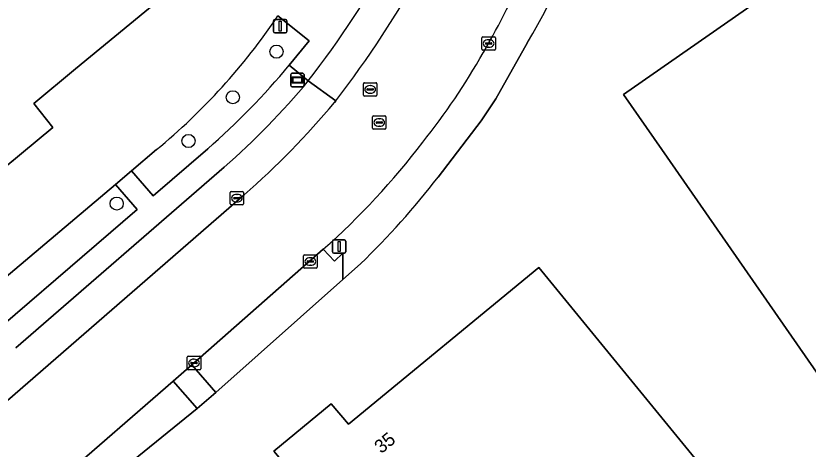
# Model space of a CAD drawing. Extents: x 156702 to 158052, y 387630 to 388992.
# Drawn here: x 157269.3 to 157328.3, y 387774.5 to 387806.8 of the extents above; entities that cross this region are included whole.
import ezdxf

# ---------------------------------------------------------------- set-up
doc = ezdxf.new("R2010")
doc.units = 0
for name, color, linetype in [('IMGEO_Boom', 7, 'Continuous'), ('IMGEO_Erf', 7, 'Continuous'), ('IMGEO_Groenvoorziening', 7, 'Continuous'), ('IMGEO_Informatiebord', 7, 'Continuous'), ('IMGEO_Kolk', 7, 'Continuous'), ('IMGEO_Lichtmast', 7, 'Continuous'), ('IMGEO_Pand', 7, 'Continuous'), ('IMGEO_Pand_nummerreeks', 7, 'Continuous'), ('IMGEO_Parkeervlak_open', 7, 'Continuous'), ('IMGEO_Rijbaan_lokaal_gesloten', 7, 'Continuous'), ('IMGEO_Rioolput', 7, 'Continuous'), ('IMGEO_Verkeersbordpaal', 7, 'Continuous'), ('IMGEO_Voetpad_open', 7, 'Continuous')]:
    doc.layers.add(name, color=color, linetype=linetype)

msp = doc.modelspace()

# ---------------------------------------------------------------- linework, layer by layer
at = {"layer": 'IMGEO_Boom'}
for centre in [(157288.701, 387804.11), (157285.448, 387800.716), (157282.148, 387797.464), (157276.803, 387792.806)]:
    msp.add_circle(centre, 0.489, dxfattribs=at)
at = {"layer": 'IMGEO_Erf'}
for points in [[(157278.484, 387870.163), (157299.316, 387844.802), (157291.542, 387838.402), (157280.697, 387829.474), (157285.889, 387823.145), (157279.697, 387818.085), (157284.76, 387811.91), (157273.737, 387802.823), (157270.622, 387800.255), (157272.057, 387798.475), (157266.039, 387793.519), (157255.901, 387805.842), (157261.926, 387810.809), (157262.25, 387810.377), (157263.979, 387811.778), (157249.792, 387829.047), (157249.636, 387829.236), (157246.596, 387832.937), (157246.438, 387833.129), (157243.382, 387836.849), (157243.219, 387837.048), (157241.16, 387839.554), (157259.836, 387854.902)], [(157363.539, 387777.795), (157348.61, 387751.927), (157317.395, 387796.828), (157314.541, 387800.934), (157324.263, 387807.695), (157318.792, 387815.594), (157321.059, 387817.16), (157323.754, 387824.051), (157322.937, 387825.336), (157325.523, 387832.18), (157329.304, 387826.757), (157336.59, 387816.266), (157336.718, 387816.356), (157339.573, 387812.251)], [(157378.748, 387694.956), (157361.772, 387681), (157364.016, 387678.262), (157358.146, 387673.452), (157342.053, 387693.048), (157343.568, 387694.292), (157319.361, 387723.831), (157319.262, 387723.952), (157297.863, 387750), (157292.107, 387757.007), (157290.591, 387755.753), (157280.605, 387767.928), (157286.246, 387772.551), (157287.377, 387771.317), (157289.551, 387773.149), (157288.491, 387774.397), (157292.77, 387777.908), (157294.05, 387776.396), (157308.228, 387788.046), (157339.41, 387750), (157344.144, 387744.224), (157340.665, 387741.338)]]:
    msp.add_lwpolyline(points, close=True, dxfattribs=at)
for points in [[(157307.397, 387804.794), (157305.043, 387800.595), (157303.942, 387798.962), (157300.737, 387794.775)], [(157265.834, 387785.07), (157276.702, 387794.234), (157277.903, 387795.246), (157279.77, 387796.82)], [(157294.955, 387788.331), (157293.629, 387787.152), (157284.18, 387778.754), (157282.784, 387777.576), (157273.993, 387770.42)]]:
    msp.add_lwpolyline(points, dxfattribs=at)
for centre, radius, start, end in [((157232.637, 387848.1), 86.397, 329.91795, 338.04808), ((157249.773, 387833.157), 47.119, 309.53976, 325.94611), ((157253.544, 387831.304), 59.679, 313.9397, 322.25903)]:
    msp.add_arc(centre, radius, start, end, dxfattribs=at)
at = {"layer": 'IMGEO_Groenvoorziening'}
for points in [[(157289.642, 387803.1), (157291.142, 387804.921), (157288.812, 387806.772)], [(157279.77, 387796.82), (157277.903, 387795.246), (157279.511, 387793.395), (157283.578, 387796.887)], [(157262.209, 387782.917), (157264.231, 387780.276), (157278.319, 387792.372), (157276.702, 387794.234), (157265.834, 387785.07)]]:
    msp.add_lwpolyline(points, dxfattribs=at)
for points in [[(157293.629, 387787.152), (157293.651, 387789.12), (157293.018, 387788.525), (157292.183, 387789.406), (157282.385, 387780.806), (157284.18, 387778.754)], [(157273.993, 387770.42), (157282.784, 387777.576), (157281.01, 387779.609), (157272.493, 387772.206)]]:
    msp.add_lwpolyline(points, close=True, dxfattribs=at)
for centre, radius, start, end in [((157249.773, 387833.157), 47.119, 309.53976, 325.94611), ((157247.514, 387838.152), 54.803, 311.15224, 320.23843)]:
    msp.add_arc(centre, radius, start, end, dxfattribs=at)
at = {"layer": 'IMGEO_Informatiebord'}
for p, q in [((157289.862, 387802.498), (157290.652, 387802.498)), ((157290.652, 387802.498), (157289.862, 387802.498)), ((157289.762, 387801.598), (157289.762, 387802.398)), ((157289.762, 387802.398), (157289.762, 387801.598)), ((157290.752, 387802.398), (157290.752, 387801.598)), ((157290.752, 387801.598), (157290.752, 387802.398)), ((157290.652, 387801.498), (157289.862, 387801.498)), ((157289.862, 387801.498), (157290.652, 387801.498))]:
    msp.add_line(p, q, dxfattribs=at)
for points in [[(157289.863, 387802.23), (157290.651, 387802.23), (157290.651, 387801.766), (157289.863, 387801.766), (157289.863, 387802.23)], [(157289.928, 387802.165), (157289.928, 387801.831), (157290.586, 387801.831), (157290.586, 387802.165), (157289.928, 387802.165)]]:
    msp.add_lwpolyline(points, dxfattribs=at)
for centre, start, end in [((157289.862, 387802.398), 90, 180), ((157289.862, 387802.398), 90, 180), ((157290.652, 387802.398), 0, 90), ((157290.652, 387802.398), 360, 90), ((157289.862, 387801.598), 180, 270), ((157289.862, 387801.598), 180, 270), ((157290.652, 387801.598), 270, 0), ((157290.652, 387801.598), 270, 0)]:
    msp.add_arc(centre, 0.1, start, end, dxfattribs=at)
at = {"layer": 'IMGEO_Kolk'}
for p, q in [((157303.997, 387804.287), (157303.997, 387805.139)), ((157304.072, 387805.213), (157304.924, 387805.213)), ((157304.485, 387804.993), (157304.51, 387804.993)), ((157304.998, 387805.139), (157304.998, 387804.287)), ((157304.924, 387804.213), (157304.072, 387804.213)), ((157304.256, 387804.707), (157304.256, 387804.719)), ((157304.694, 387804.67), (157304.296, 387804.67)), ((157304.299, 387804.756), (157304.697, 387804.756)), ((157304.508, 387804.433), (157304.483, 387804.433)), ((157304.74, 387804.719), (157304.74, 387804.707)), ((157285.251, 387792.783), (157285.251, 387793.635)), ((157285.326, 387793.709), (157286.178, 387793.709)), ((157286.252, 387793.635), (157286.252, 387792.783)), ((157285.51, 387793.203), (157285.51, 387793.215)), ((157285.948, 387793.166), (157285.55, 387793.166)), ((157285.553, 387793.252), (157285.951, 387793.252)), ((157285.739, 387793.489), (157285.764, 387793.489)), ((157285.994, 387793.215), (157285.994, 387793.203)), ((157286.178, 387792.709), (157285.326, 387792.709)), ((157285.762, 387792.929), (157285.737, 387792.929)), ((157290.723, 387788.073), (157290.723, 387788.925)), ((157290.798, 387788.999), (157291.65, 387788.999)), ((157291.724, 387788.925), (157291.724, 387788.073)), ((157290.982, 387788.493), (157290.982, 387788.505)), ((157291.42, 387788.456), (157291.022, 387788.456)), ((157291.025, 387788.542), (157291.423, 387788.542)), ((157291.211, 387788.779), (157291.236, 387788.779)), ((157291.466, 387788.505), (157291.466, 387788.493)), ((157291.65, 387787.999), (157290.798, 387787.999)), ((157291.234, 387788.219), (157291.209, 387788.219)), ((157282.058, 387780.526), (157282.058, 387781.378)), ((157282.133, 387781.452), (157282.985, 387781.452)), ((157282.546, 387781.232), (157282.571, 387781.232)), ((157283.059, 387781.378), (157283.059, 387780.526)), ((157282.317, 387780.946), (157282.317, 387780.958)), ((157282.755, 387780.909), (157282.357, 387780.909)), ((157282.36, 387780.995), (157282.758, 387780.995)), ((157282.569, 387780.672), (157282.544, 387780.672)), ((157282.801, 387780.958), (157282.801, 387780.946)), ((157282.985, 387780.452), (157282.133, 387780.452))]:
    msp.add_line(p, q, dxfattribs=at)
for points in [[(157303.997, 387804.287), (157303.997, 387805.139)], [(157304.072, 387805.213), (157304.924, 387805.213)], [(157304.998, 387805.139), (157304.998, 387804.287)], [(157304.924, 387804.213), (157304.072, 387804.213)], [(157285.251, 387792.783), (157285.251, 387793.635)], [(157285.326, 387793.709), (157286.178, 387793.709)], [(157286.252, 387793.635), (157286.252, 387792.783)], [(157286.178, 387792.709), (157285.326, 387792.709)], [(157290.723, 387788.073), (157290.723, 387788.925)], [(157290.798, 387788.999), (157291.65, 387788.999)], [(157291.724, 387788.925), (157291.724, 387788.073)], [(157291.65, 387787.999), (157290.798, 387787.999)], [(157282.058, 387780.526), (157282.058, 387781.378)], [(157282.133, 387781.452), (157282.985, 387781.452)], [(157283.059, 387781.378), (157283.059, 387780.526)], [(157282.985, 387780.452), (157282.133, 387780.452)]]:
    msp.add_lwpolyline(points, dxfattribs=at)
for centre, radius, start, end in [((157304.074, 387805.137), 0.0765, 91.55205, 178.44795), ((157304.074, 387805.137), 0.0765, 91.55205, 178.44795), ((157304.922, 387805.137), 0.0765, 1.55205, 88.44795), ((157304.922, 387805.137), 0.0765, 1.55205, 88.44795), ((157304.074, 387804.289), 0.0765, 181.55205, 268.44795), ((157304.074, 387804.289), 0.0765, 181.55205, 268.44795), ((157304.296, 387804.716), 0.0403, 85.87752, 175.75265), ((157304.293, 387804.706), 0.0366, 178.93798, 274.71019), ((157304.697, 387804.713), 0.043, 264.86636, 352.45326), ((157304.701, 387804.718), 0.0386, 1.73085, 96.63898), ((157304.922, 387804.289), 0.0765, 271.55205, 358.44795), ((157304.922, 387804.289), 0.0765, 271.55205, 358.44795), ((157285.328, 387793.633), 0.0765, 91.55205, 178.44795), ((157285.328, 387793.633), 0.0765, 91.55205, 178.44795), ((157286.176, 387793.633), 0.0765, 1.55205, 88.44795), ((157286.176, 387793.633), 0.0765, 1.55205, 88.44795), ((157285.55, 387793.212), 0.0403, 85.87752, 175.75265), ((157285.547, 387793.202), 0.0366, 178.93798, 274.71019), ((157285.951, 387793.209), 0.043, 264.86636, 352.45326), ((157285.955, 387793.214), 0.0386, 1.73085, 96.63898), ((157285.328, 387792.785), 0.0765, 181.55205, 268.44795), ((157285.328, 387792.785), 0.0765, 181.55205, 268.44795), ((157286.176, 387792.785), 0.0765, 271.55205, 358.44795), ((157286.176, 387792.785), 0.0765, 271.55205, 358.44795), ((157290.8, 387788.923), 0.0765, 91.55205, 178.44795), ((157290.8, 387788.923), 0.0765, 91.55205, 178.44795), ((157291.648, 387788.923), 0.0765, 1.55205, 88.44795), ((157291.648, 387788.923), 0.0765, 1.55205, 88.44795), ((157291.022, 387788.502), 0.0403, 85.87752, 175.75265), ((157291.019, 387788.492), 0.0366, 178.93798, 274.71019), ((157291.423, 387788.499), 0.043, 264.86636, 352.45326), ((157291.427, 387788.504), 0.0386, 1.73085, 96.63898), ((157290.8, 387788.075), 0.0765, 181.55205, 268.44795), ((157290.8, 387788.075), 0.0765, 181.55205, 268.44795), ((157291.648, 387788.075), 0.0765, 271.55205, 358.44795), ((157291.648, 387788.075), 0.0765, 271.55205, 358.44795), ((157282.135, 387781.376), 0.0765, 91.55205, 178.44795), ((157282.135, 387781.376), 0.0765, 91.55205, 178.44795), ((157282.983, 387781.376), 0.0765, 1.55205, 88.44795), ((157282.983, 387781.376), 0.0765, 1.55205, 88.44795), ((157282.357, 387780.955), 0.0403, 85.87752, 175.75265), ((157282.354, 387780.945), 0.0366, 178.93798, 274.71019), ((157282.758, 387780.952), 0.043, 264.86636, 352.45326), ((157282.762, 387780.957), 0.0386, 1.73085, 96.63898), ((157282.135, 387780.528), 0.0765, 181.55205, 268.44795), ((157282.135, 387780.528), 0.0765, 181.55205, 268.44795), ((157282.983, 387780.528), 0.0765, 271.55205, 358.44795), ((157282.983, 387780.528), 0.0765, 271.55205, 358.44795)]:
    msp.add_arc(centre, radius, start, end, dxfattribs=at)
for centre, major_axis, ratio, start_param, end_param in [((157304.484, 387804.713), (-0.387, 0.002), 0.722429, 4.712389, 7.853982), ((157304.509, 387804.713), (-0.39, 0.002), 0.717154, 1.570796, 4.712389), ((157285.738, 387793.209), (-0.387, 0.002), 0.722429, 4.712389, 7.853982), ((157285.763, 387793.209), (-0.39, 0.002), 0.717154, 1.570796, 4.712389), ((157291.21, 387788.499), (-0.387, 0.002), 0.722429, 4.712389, 7.853982), ((157291.235, 387788.499), (-0.39, 0.002), 0.717154, 1.570796, 4.712389), ((157282.545, 387780.952), (-0.387, 0.002), 0.722429, 4.712389, 7.853982), ((157282.57, 387780.952), (-0.39, 0.002), 0.717154, 1.570796, 4.712389)]:
    msp.add_ellipse(centre, major_axis=major_axis, ratio=ratio, start_param=start_param, end_param=end_param, dxfattribs=at)
at = {"layer": 'IMGEO_Lichtmast'}
for p, q in [((157292.865, 387789.215), (157292.865, 387790.015)), ((157292.865, 387790.015), (157292.865, 387789.215)), ((157292.965, 387790.115), (157293.755, 387790.115)), ((157293.755, 387790.115), (157292.965, 387790.115)), ((157293.855, 387790.015), (157293.855, 387789.215)), ((157293.855, 387789.215), (157293.855, 387790.015)), ((157293.755, 387789.115), (157292.965, 387789.115)), ((157292.965, 387789.115), (157293.755, 387789.115))]:
    msp.add_line(p, q, dxfattribs=at)
msp.add_lwpolyline([(157293.285, 387789.99), (157293.435, 387789.99), (157293.435, 387789.24), (157293.285, 387789.24), (157293.285, 387789.99)], dxfattribs=at)
for centre, start, end in [((157292.965, 387790.015), 90, 180), ((157292.965, 387790.015), 90, 180), ((157293.755, 387790.015), 0, 90), ((157293.755, 387790.015), 360, 90), ((157292.965, 387789.215), 180, 270), ((157292.965, 387789.215), 180, 270), ((157293.755, 387789.215), 270, 0), ((157293.755, 387789.215), 270, 0)]:
    msp.add_arc(centre, 0.1, start, end, dxfattribs=at)
at = {"layer": 'IMGEO_Pand'}
for points in [[(157249.792, 387829.047), (157263.979, 387811.778), (157262.25, 387810.377), (157261.926, 387810.809), (157255.901, 387805.842), (157266.039, 387793.519), (157272.057, 387798.475), (157270.622, 387800.255), (157273.737, 387802.823), (157284.76, 387811.91), (157279.697, 387818.085), (157285.889, 387823.145), (157280.697, 387829.474), (157291.542, 387838.402), (157299.316, 387844.802), (157278.484, 387870.163), (157259.836, 387854.902), (157241.16, 387839.554), (157243.219, 387837.048), (157243.382, 387836.849), (157246.438, 387833.129), (157246.596, 387832.937), (157249.636, 387829.236)], [(157336.718, 387816.356), (157336.59, 387816.266), (157329.304, 387826.757), (157325.523, 387832.18), (157322.937, 387825.336), (157323.754, 387824.051), (157321.059, 387817.16), (157318.792, 387815.594), (157324.263, 387807.695), (157314.541, 387800.934), (157317.395, 387796.828), (157348.61, 387751.927), (157363.539, 387777.795), (157339.573, 387812.251)], [(157319.361, 387723.831), (157340.665, 387741.338), (157344.144, 387744.224), (157339.41, 387750), (157308.228, 387788.046), (157294.05, 387776.396), (157292.77, 387777.908), (157288.491, 387774.397), (157289.551, 387773.149), (157287.377, 387771.317), (157286.246, 387772.551), (157280.605, 387767.928), (157290.591, 387755.753), (157292.107, 387757.007), (157297.863, 387750), (157319.262, 387723.952)]]:
    msp.add_lwpolyline(points, close=True, dxfattribs=at)
at = {"layer": 'IMGEO_Parkeervlak_open'}
for points in [[(157293.014, 387800.321), (157293.119, 387800.457), (157291.063, 387801.929)], [(157284.808, 387795.507), (157269.292, 387782.069)], [(157268.085, 387777.663), (157286.301, 387793.452)]]:
    msp.add_lwpolyline(points, dxfattribs=at)
for centre, radius, start, end in [((157245.148, 387840.393), 59.897, 311.46298, 320.0465), ((157244.168, 387841.343), 63.786, 311.34034, 319.97578)]:
    msp.add_arc(centre, radius, start, end, dxfattribs=at)
at = {"layer": 'IMGEO_Rijbaan_lokaal_gesloten'}
for points in [[(157304.091, 387804.034), (157304.594, 387804.903)], [(157293.119, 387800.457), (157293.014, 387800.321)], [(157286.301, 387793.452), (157268.085, 387777.663), (157267.868, 387777.475), (157266.365, 387776.435), (157265.591, 387776.039), (157265.488, 387775.964)], [(157281.01, 387779.609), (157282.385, 387780.806), (157292.183, 387789.406)], [(157270.059, 387770.045), (157270.681, 387770.652), (157272.381, 387772.11), (157272.493, 387772.206), (157281.01, 387779.609)]]:
    msp.add_lwpolyline(points, dxfattribs=at)
for centre, radius, start, end in [((157231.904, 387847.749), 77.355, 322.31186, 339.92433), ((157200.407, 387861.75), 118.687, 331.382, 338.18195), ((157260.794, 387828.461), 49.712, 321.29212, 330.56876), ((157244.168, 387841.343), 63.786, 311.34034, 319.97578), ((157255.479, 387830.935), 55.424, 311.47006, 322.73243)]:
    msp.add_arc(centre, radius, start, end, dxfattribs=at)
at = {"layer": 'IMGEO_Rioolput'}
for p, q in [((157295.176, 387800.874), (157295.176, 387801.726)), ((157295.251, 387801.8), (157296.103, 387801.8)), ((157295.435, 387801.294), (157295.435, 387801.306)), ((157295.873, 387801.257), (157295.475, 387801.257)), ((157295.478, 387801.343), (157295.876, 387801.343)), ((157295.664, 387801.58), (157295.689, 387801.58)), ((157295.919, 387801.306), (157295.919, 387801.294)), ((157296.177, 387801.726), (157296.177, 387800.874)), ((157296.103, 387800.8), (157295.251, 387800.8)), ((157295.687, 387801.02), (157295.662, 387801.02)), ((157295.852, 387798.409), (157295.852, 387799.261)), ((157295.927, 387799.335), (157296.779, 387799.335)), ((157296.154, 387798.878), (157296.552, 387798.878)), ((157296.34, 387799.115), (157296.365, 387799.115)), ((157296.853, 387799.261), (157296.853, 387798.409)), ((157296.779, 387798.335), (157295.927, 387798.335)), ((157296.111, 387798.829), (157296.111, 387798.841)), ((157296.549, 387798.792), (157296.151, 387798.792)), ((157296.363, 387798.555), (157296.338, 387798.555)), ((157296.595, 387798.841), (157296.595, 387798.829))]:
    msp.add_line(p, q, dxfattribs=at)
for points in [[(157295.176, 387800.874), (157295.176, 387801.726)], [(157295.251, 387801.8), (157296.103, 387801.8)], [(157296.177, 387801.726), (157296.177, 387800.874)], [(157296.103, 387800.8), (157295.251, 387800.8)], [(157295.852, 387798.409), (157295.852, 387799.261)], [(157295.927, 387799.335), (157296.779, 387799.335)], [(157296.853, 387799.261), (157296.853, 387798.409)], [(157296.779, 387798.335), (157295.927, 387798.335)]]:
    msp.add_lwpolyline(points, dxfattribs=at)
for centre, radius, start, end in [((157295.253, 387801.724), 0.0765, 91.55205, 178.44795), ((157295.253, 387801.724), 0.0765, 91.55205, 178.44795), ((157295.475, 387801.303), 0.0403, 85.87752, 175.75265), ((157295.472, 387801.293), 0.0366, 178.93798, 274.71019), ((157295.876, 387801.3), 0.043, 264.86636, 352.45326), ((157295.88, 387801.305), 0.0386, 1.73085, 96.63898), ((157296.101, 387801.724), 0.0765, 1.55205, 88.44795), ((157296.101, 387801.724), 0.0765, 1.55205, 88.44795), ((157295.253, 387800.876), 0.0765, 181.55205, 268.44795), ((157295.253, 387800.876), 0.0765, 181.55205, 268.44795), ((157296.101, 387800.876), 0.0765, 271.55205, 358.44795), ((157296.101, 387800.876), 0.0765, 271.55205, 358.44795), ((157295.929, 387799.259), 0.0765, 91.55205, 178.44795), ((157295.929, 387799.259), 0.0765, 91.55205, 178.44795), ((157296.151, 387798.838), 0.0403, 85.87752, 175.75265), ((157296.556, 387798.84), 0.0386, 1.73085, 96.63898), ((157296.777, 387799.259), 0.0765, 1.55205, 88.44795), ((157296.777, 387799.259), 0.0765, 1.55205, 88.44795), ((157295.929, 387798.411), 0.0765, 181.55205, 268.44795), ((157295.929, 387798.411), 0.0765, 181.55205, 268.44795), ((157296.148, 387798.828), 0.0366, 178.93798, 274.71019), ((157296.552, 387798.835), 0.043, 264.86636, 352.45326), ((157296.777, 387798.411), 0.0765, 271.55205, 358.44795), ((157296.777, 387798.411), 0.0765, 271.55205, 358.44795)]:
    msp.add_arc(centre, radius, start, end, dxfattribs=at)
for centre, major_axis, ratio, start_param, end_param in [((157295.663, 387801.3), (-0.387, 0.002), 0.722429, 4.712389, 7.853982), ((157295.688, 387801.3), (-0.39, 0.002), 0.717154, 1.570796, 4.712389), ((157296.339, 387798.835), (-0.387, 0.002), 0.722429, 4.712389, 7.853982), ((157296.364, 387798.835), (-0.39, 0.002), 0.717154, 1.570796, 4.712389)]:
    msp.add_ellipse(centre, major_axis=major_axis, ratio=ratio, start_param=start_param, end_param=end_param, dxfattribs=at)
at = {"layer": 'IMGEO_Verkeersbordpaal'}
for p, q in [((157288.475, 387805.607), (157288.475, 387806.407)), ((157288.475, 387806.407), (157288.475, 387805.607)), ((157288.575, 387806.507), (157289.365, 387806.507)), ((157289.365, 387806.507), (157288.575, 387806.507)), ((157289.465, 387806.407), (157289.465, 387805.607)), ((157289.465, 387805.607), (157289.465, 387806.407)), ((157289.365, 387805.507), (157288.575, 387805.507)), ((157288.575, 387805.507), (157289.365, 387805.507))]:
    msp.add_line(p, q, dxfattribs=at)
msp.add_lwpolyline([(157288.895, 387806.382), (157289.045, 387806.382), (157289.045, 387805.632), (157288.895, 387805.632), (157288.895, 387806.382)], dxfattribs=at)
for centre, start, end in [((157288.575, 387806.407), 90, 180), ((157288.575, 387806.407), 90, 180), ((157289.365, 387806.407), 0, 90), ((157289.365, 387806.407), 360, 90), ((157288.575, 387805.607), 180, 270), ((157288.575, 387805.607), 180, 270), ((157289.365, 387805.607), 270, 0), ((157289.365, 387805.607), 270, 0)]:
    msp.add_arc(centre, 0.1, start, end, dxfattribs=at)
at = {"layer": 'IMGEO_Voetpad_open'}
for points in [[(157288.812, 387806.772), (157291.142, 387804.921), (157289.642, 387803.1), (157291.063, 387801.929)], [(157300.737, 387794.775), (157303.942, 387798.962), (157305.043, 387800.595), (157307.397, 387804.794)], [(157304.594, 387804.903), (157304.091, 387804.034)], [(157291.063, 387801.929), (157289.642, 387803.1)], [(157291.063, 387801.929), (157293.119, 387800.457)], [(157283.578, 387796.887), (157279.511, 387793.395), (157277.903, 387795.246), (157276.702, 387794.234), (157278.319, 387792.372), (157264.231, 387780.276)], [(157269.292, 387782.069), (157284.808, 387795.507)], [(157292.183, 387789.406), (157293.018, 387788.525), (157293.651, 387789.12), (157293.629, 387787.152), (157294.955, 387788.331)]]:
    msp.add_lwpolyline(points, dxfattribs=at)
msp.add_lwpolyline([(157281.01, 387779.609), (157282.784, 387777.576), (157284.18, 387778.754), (157282.385, 387780.806)], close=True, dxfattribs=at)
for centre, radius, start, end in [((157231.182, 387848.181), 75.663, 322.31758, 339.85782), ((157231.182, 387848.181), 75.663, 322.31758, 339.85782), ((157231.904, 387847.749), 77.355, 322.31186, 339.92433), ((157200.407, 387861.75), 118.687, 331.382, 338.18195), ((157232.637, 387848.1), 86.397, 329.91795, 338.04808), ((157260.794, 387828.461), 49.712, 321.29212, 330.56876), ((157247.514, 387838.152), 54.803, 311.15224, 320.23843), ((157245.148, 387840.393), 59.897, 311.46298, 320.0465), ((157255.479, 387830.935), 55.424, 311.47006, 322.73243), ((157253.544, 387831.304), 59.679, 313.9397, 322.25903)]:
    msp.add_arc(centre, radius, start, end, dxfattribs=at)

# ---------------------------------------------------------------- texts
at = {"layer": 'IMGEO_Pand_nummerreeks'}
msp.add_text('35', height=1, rotation=39.40804, dxfattribs=at).set_placement((157296.501, 387774.164))

doc.saveas('drawing.dxf')
